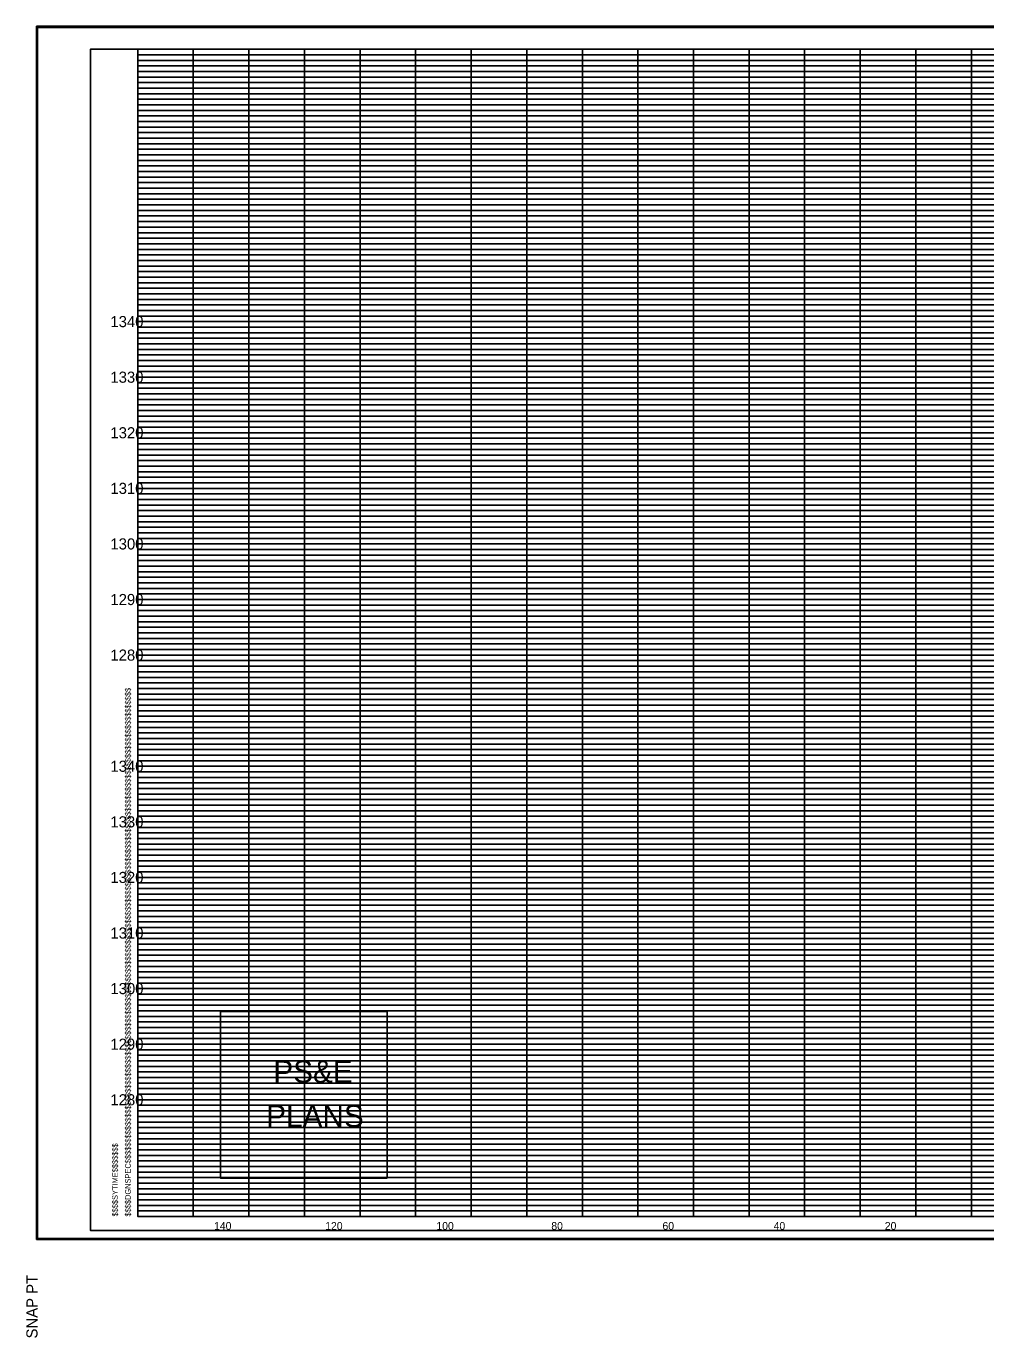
# Model space of a CAD drawing. Extents: x 980 to 1324, y 978 to 2847.
# Drawn here: x 979.9 to 1152.6, y 1248.2 to 1484.1 of the extents above; entities that cross this region are included whole.
import ezdxf

# ---------------------------------------------------------------- set-up
doc = ezdxf.new("R2010")
doc.units = 0
for name, color, linetype in [('DESIGN - SHEET - Corner Text', 7, 'Continuous'), ('DESIGN - SHEET - Light Grid', 7, 'Continuous'), ('DESIGN - SHEET - Linework', 7, 'Continuous'), ('DESIGN - SHEET - Plot Shape', 7, 'Continuous'), ('DESIGN - TYPICAL - Text', 7, 'Continuous')]:
    doc.layers.add(name, color=color, linetype=linetype)

# ---------------------------------------------------------------- blocks, each defined once
blk = doc.blocks.new('XSTSHT')
at = {"layer": 'DESIGN - SHEET - Light Grid'}
for p, q in [((0, 20.9), (8, 20.9)), ((0, 20.8), (8, 20.8)), ((8, 20.9), (16, 20.9)), ((8, 20.8), (16, 20.8)), ((0, 20.7), (8, 20.7)), ((0, 20.6), (8, 20.6)), ((8, 20.7), (16, 20.7)), ((8, 20.6), (16, 20.6)), ((0, 20.5), (8, 20.5)), ((0, 20.4), (8, 20.4)), ((0, 20.3), (8, 20.3)), ((8, 20.5), (16, 20.5)), ((8, 20.4), (16, 20.4)), ((8, 20.3), (16, 20.3)), ((0, 20.2), (8, 20.2)), ((0, 20.1), (8, 20.1)), ((8, 20.2), (16, 20.2)), ((8, 20.1), (16, 20.1)), ((0, 19.9), (8, 19.9)), ((8, 19.9), (16, 19.9)), ((0, 19.8), (8, 19.8)), ((0, 19.7), (8, 19.7)), ((0, 19.6), (8, 19.6)), ((8, 19.8), (16, 19.8)), ((8, 19.7), (16, 19.7)), ((8, 19.6), (16, 19.6)), ((0, 19.5), (8, 19.5)), ((0, 19.4), (8, 19.4)), ((8, 19.5), (16, 19.5)), ((8, 19.4), (16, 19.4)), ((0, 19.3), (8, 19.3)), ((0, 19.2), (8, 19.2)), ((8, 19.3), (16, 19.3)), ((8, 19.2), (16, 19.2)), ((0, 19.1), (8, 19.1)), ((0, 18.9), (8, 18.9)), ((8, 19.1), (16, 19.1)), ((8, 18.9), (16, 18.9)), ((0, 18.8), (8, 18.8)), ((0, 18.7), (8, 18.7)), ((8, 18.8), (16, 18.8)), ((8, 18.7), (16, 18.7)), ((0, 18.6), (8, 18.6)), ((0, 18.5), (8, 18.5)), ((8, 18.6), (16, 18.6)), ((8, 18.5), (16, 18.5)), ((0, 18.4), (8, 18.4)), ((0, 18.3), (8, 18.3)), ((0, 18.2), (8, 18.2)), ((8, 18.4), (16, 18.4)), ((8, 18.3), (16, 18.3)), ((8, 18.2), (16, 18.2)), ((0, 18.1), (8, 18.1)), ((8, 18.1), (16, 18.1)), ((0, 17.9), (8, 17.9)), ((0, 17.8), (8, 17.8)), ((0, 17.7), (8, 17.7)), ((8, 17.9), (16, 17.9)), ((8, 17.8), (16, 17.8)), ((8, 17.7), (16, 17.7)), ((0, 17.6), (8, 17.6)), ((0, 17.5), (8, 17.5)), ((8, 17.6), (16, 17.6)), ((8, 17.5), (16, 17.5)), ((0, 17.4), (8, 17.4)), ((0, 17.3), (8, 17.3)), ((8, 17.4), (16, 17.4)), ((8, 17.3), (16, 17.3)), ((0, 17.2), (8, 17.2)), ((0, 17.1), (8, 17.1)), ((8, 17.2), (16, 17.2)), ((8, 17.1), (16, 17.1)), ((0, 16.9), (8, 16.9)), ((0, 16.8), (8, 16.8)), ((8, 16.9), (16, 16.9)), ((8, 16.8), (16, 16.8)), ((0, 16.7), (8, 16.7)), ((0, 16.6), (8, 16.6)), ((8, 16.7), (16, 16.7)), ((8, 16.6), (16, 16.6)), ((0, 16.5), (8, 16.5)), ((0, 16.4), (8, 16.4)), ((0, 16.3), (8, 16.3)), ((8, 16.5), (16, 16.5)), ((8, 16.4), (16, 16.4)), ((8, 16.3), (16, 16.3)), ((0, 16.2), (8, 16.2)), ((0, 16.1), (8, 16.1)), ((8, 16.2), (16, 16.2)), ((8, 16.1), (16, 16.1)), ((0, 15.9), (8, 15.9)), ((8, 15.9), (16, 15.9)), ((0, 15.8), (8, 15.8)), ((0, 15.7), (8, 15.7)), ((0, 15.6), (8, 15.6)), ((8, 15.8), (16, 15.8)), ((8, 15.7), (16, 15.7)), ((8, 15.6), (16, 15.6)), ((0, 15.5), (8, 15.5)), ((0, 15.4), (8, 15.4)), ((8, 15.5), (16, 15.5)), ((8, 15.4), (16, 15.4)), ((0, 15.3), (8, 15.3)), ((0, 15.2), (8, 15.2)), ((8, 15.3), (16, 15.3)), ((8, 15.2), (16, 15.2)), ((0, 15.1), (8, 15.1)), ((0, 14.9), (8, 14.9)), ((8, 15.1), (16, 15.1)), ((8, 14.9), (16, 14.9)), ((0, 14.8), (8, 14.8)), ((0, 14.7), (8, 14.7)), ((8, 14.8), (16, 14.8)), ((8, 14.7), (16, 14.7)), ((0, 14.6), (8, 14.6)), ((0, 14.5), (8, 14.5)), ((0, 14.4), (8, 14.4)), ((8, 14.6), (16, 14.6)), ((8, 14.5), (16, 14.5)), ((8, 14.4), (16, 14.4)), ((0, 14.3), (8, 14.3)), ((0, 14.2), (8, 14.2)), ((8, 14.3), (16, 14.3)), ((8, 14.2), (16, 14.2)), ((0, 14.1), (8, 14.1)), ((8, 14.1), (16, 14.1)), ((0, 13.9), (8, 13.9)), ((0, 13.8), (8, 13.8)), ((0, 13.7), (8, 13.7)), ((8, 13.9), (16, 13.9)), ((8, 13.8), (16, 13.8)), ((8, 13.7), (16, 13.7)), ((0, 13.6), (8, 13.6)), ((0, 13.5), (8, 13.5)), ((8, 13.6), (16, 13.6)), ((8, 13.5), (16, 13.5)), ((0, 13.4), (8, 13.4)), ((0, 13.3), (8, 13.3)), ((8, 13.4), (16, 13.4)), ((8, 13.3), (16, 13.3)), ((0, 13.2), (8, 13.2)), ((0, 13.1), (8, 13.1)), ((8, 13.2), (16, 13.2)), ((8, 13.1), (16, 13.1)), ((0, 12.9), (8, 12.9)), ((0, 12.8), (8, 12.8)), ((8, 12.9), (16, 12.9)), ((8, 12.8), (16, 12.8)), ((0, 12.7), (8, 12.7)), ((0, 12.6), (8, 12.6)), ((8, 12.7), (16, 12.7)), ((8, 12.6), (16, 12.6)), ((0, 12.5), (8, 12.5)), ((0, 12.4), (8, 12.4)), ((0, 12.3), (8, 12.3)), ((8, 12.5), (16, 12.5)), ((8, 12.4), (16, 12.4)), ((8, 12.3), (16, 12.3)), ((0, 12.2), (8, 12.2)), ((0, 12.1), (8, 12.1)), ((8, 12.2), (16, 12.2)), ((8, 12.1), (16, 12.1)), ((0, 11.9), (8, 11.9)), ((0, 11.8), (8, 11.8)), ((8, 11.9), (16, 11.9)), ((8, 11.8), (16, 11.8)), ((0, 11.7), (8, 11.7)), ((0, 11.6), (8, 11.6)), ((8, 11.7), (16, 11.7)), ((8, 11.6), (16, 11.6)), ((0, 11.5), (8, 11.5)), ((0, 11.4), (8, 11.4)), ((8, 11.5), (16, 11.5)), ((8, 11.4), (16, 11.4)), ((0, 11.3), (8, 11.3)), ((0, 11.2), (8, 11.2)), ((0, 11.1), (8, 11.1)), ((8, 11.3), (16, 11.3)), ((8, 11.2), (16, 11.2)), ((8, 11.1), (16, 11.1)), ((0, 10.9), (8, 10.9)), ((8, 10.9), (16, 10.9)), ((0, 10.8), (8, 10.8)), ((0, 10.7), (8, 10.7)), ((8, 10.8), (16, 10.8)), ((8, 10.7), (16, 10.7)), ((0, 10.6), (8, 10.6)), ((0, 10.5), (8, 10.5)), ((0, 10.4), (8, 10.4)), ((8, 10.6), (16, 10.6)), ((8, 10.5), (16, 10.5)), ((8, 10.4), (16, 10.4)), ((0, 10.3), (8, 10.3)), ((0, 10.2), (8, 10.2)), ((8, 10.3), (16, 10.3)), ((8, 10.2), (16, 10.2)), ((0, 10.1), (8, 10.1)), ((8, 10.1), (16, 10.1)), ((0, 9.9), (8, 9.9)), ((0, 9.8), (8, 9.8)), ((0, 9.7), (8, 9.7)), ((8, 9.9), (16, 9.9)), ((8, 9.8), (16, 9.8)), ((8, 9.7), (16, 9.7)), ((0, 9.6), (8, 9.6)), ((0, 9.5), (8, 9.5)), ((8, 9.6), (16, 9.6)), ((8, 9.5), (16, 9.5)), ((0, 9.4), (8, 9.4)), ((0, 9.3), (8, 9.3)), ((8, 9.4), (16, 9.4)), ((8, 9.3), (16, 9.3)), ((0, 9.2), (8, 9.2)), ((0, 9.1), (8, 9.1)), ((8, 9.2), (16, 9.2)), ((8, 9.1), (16, 9.1)), ((0, 8.9), (8, 8.9)), ((0, 8.8), (8, 8.8)), ((8, 8.9), (16, 8.9)), ((8, 8.8), (16, 8.8)), ((0, 8.7), (8, 8.7)), ((0, 8.6), (8, 8.6)), ((0, 8.5), (8, 8.5)), ((8, 8.7), (16, 8.7)), ((8, 8.6), (16, 8.6)), ((8, 8.5), (16, 8.5)), ((0, 8.4), (8, 8.4)), ((0, 8.3), (8, 8.3)), ((8, 8.4), (16, 8.4)), ((8, 8.3), (16, 8.3)), ((0, 8.2), (8, 8.2)), ((0, 8.1), (8, 8.1)), ((8, 8.2), (16, 8.2)), ((8, 8.1), (16, 8.1)), ((0, 7.9), (8, 7.9)), ((0, 7.8), (8, 7.8)), ((8, 7.9), (16, 7.9)), ((8, 7.8), (16, 7.8)), ((0, 7.7), (8, 7.7)), ((0, 7.6), (8, 7.6)), ((8, 7.7), (16, 7.7)), ((8, 7.6), (16, 7.6)), ((0, 7.5), (8, 7.5)), ((0, 7.4), (8, 7.4)), ((8, 7.5), (16, 7.5)), ((8, 7.4), (16, 7.4)), ((0, 7.3), (8, 7.3)), ((0, 7.2), (8, 7.2)), ((0, 7.1), (8, 7.1)), ((8, 7.3), (16, 7.3)), ((8, 7.2), (16, 7.2)), ((8, 7.1), (16, 7.1)), ((0, 6.9), (8, 6.9)), ((8, 6.9), (16, 6.9)), ((0, 6.8), (8, 6.8)), ((0, 6.7), (8, 6.7)), ((8, 6.8), (16, 6.8)), ((8, 6.7), (16, 6.7)), ((0, 6.6), (8, 6.6)), ((0, 6.5), (8, 6.5)), ((0, 6.4), (8, 6.4)), ((8, 6.6), (16, 6.6)), ((8, 6.5), (16, 6.5)), ((8, 6.4), (16, 6.4)), ((0, 6.3), (8, 6.3)), ((0, 6.2), (8, 6.2)), ((8, 6.3), (16, 6.3)), ((8, 6.2), (16, 6.2)), ((0, 6.1), (8, 6.1)), ((0, 5.9), (8, 5.9)), ((8, 6.1), (16, 6.1)), ((8, 5.9), (16, 5.9)), ((0, 5.8), (8, 5.8)), ((0, 5.7), (8, 5.7)), ((8, 5.8), (16, 5.8)), ((8, 5.7), (16, 5.7)), ((0, 5.6), (8, 5.6)), ((0, 5.5), (8, 5.5)), ((8, 5.6), (16, 5.6)), ((8, 5.5), (16, 5.5)), ((0, 5.4), (8, 5.4)), ((0, 5.3), (8, 5.3)), ((0, 5.2), (8, 5.2)), ((8, 5.4), (16, 5.4)), ((8, 5.3), (16, 5.3)), ((8, 5.2), (16, 5.2)), ((0, 5.1), (8, 5.1)), ((8, 5.1), (16, 5.1)), ((0, 4.9), (8, 4.9)), ((0, 4.8), (8, 4.8)), ((8, 4.9), (16, 4.9)), ((8, 4.8), (16, 4.8)), ((0, 4.7), (8, 4.7)), ((0, 4.6), (8, 4.6)), ((0, 4.5), (8, 4.5)), ((8, 4.7), (16, 4.7)), ((8, 4.6), (16, 4.6)), ((8, 4.5), (16, 4.5)), ((0, 4.4), (8, 4.4)), ((0, 4.3), (8, 4.3)), ((8, 4.4), (16, 4.4)), ((8, 4.3), (16, 4.3)), ((0, 4.2), (8, 4.2)), ((0, 4.1), (8, 4.1)), ((8, 4.2), (16, 4.2)), ((8, 4.1), (16, 4.1)), ((0, 3.9), (8, 3.9)), ((0, 3.8), (8, 3.8)), ((8, 3.9), (16, 3.9)), ((8, 3.8), (16, 3.8)), ((0, 3.7), (8, 3.7)), ((0, 3.6), (8, 3.6)), ((8, 3.7), (16, 3.7)), ((8, 3.6), (16, 3.6)), ((0, 3.5), (8, 3.5)), ((0, 3.4), (8, 3.4)), ((8, 3.5), (16, 3.5)), ((8, 3.4), (16, 3.4)), ((0, 3.3), (8, 3.3)), ((0, 3.2), (8, 3.2)), ((0, 3.1), (8, 3.1)), ((8, 3.3), (16, 3.3)), ((8, 3.2), (16, 3.2)), ((8, 3.1), (16, 3.1)), ((0, 2.9), (8, 2.9)), ((8, 2.9), (16, 2.9)), ((0, 2.8), (8, 2.8)), ((0, 2.7), (8, 2.7)), ((0, 2.6), (8, 2.6)), ((8, 2.8), (16, 2.8)), ((8, 2.7), (16, 2.7)), ((8, 2.6), (16, 2.6)), ((0, 2.5), (8, 2.5)), ((0, 2.4), (8, 2.4)), ((8, 2.5), (16, 2.5)), ((8, 2.4), (16, 2.4)), ((0, 2.3), (8, 2.3)), ((0, 2.2), (8, 2.2)), ((8, 2.3), (16, 2.3)), ((8, 2.2), (16, 2.2)), ((0, 2.1), (8, 2.1)), ((0, 1.9), (8, 1.9)), ((8, 2.1), (16, 2.1)), ((8, 1.9), (16, 1.9)), ((0, 1.8), (8, 1.8)), ((0, 1.7), (8, 1.7)), ((8, 1.8), (16, 1.8)), ((8, 1.7), (16, 1.7)), ((0, 1.6), (8, 1.6)), ((0, 1.5), (8, 1.5)), ((8, 1.6), (16, 1.6)), ((8, 1.5), (16, 1.5)), ((0, 1.4), (8, 1.4)), ((0, 1.3), (8, 1.3)), ((0, 1.2), (8, 1.2)), ((8, 1.4), (16, 1.4)), ((8, 1.3), (16, 1.3)), ((8, 1.2), (16, 1.2)), ((0, 1.1), (8, 1.1)), ((8, 1.1), (16, 1.1)), ((0, 0.9), (8, 0.9)), ((0, 0.8), (8, 0.8)), ((8, 0.9), (16, 0.9)), ((8, 0.8), (16, 0.8)), ((0, 0.7), (8, 0.7)), ((0, 0.6), (8, 0.6)), ((0, 0.5), (8, 0.5)), ((8, 0.7), (16, 0.7)), ((8, 0.6), (16, 0.6)), ((8, 0.5), (16, 0.5)), ((0, 0.4), (8, 0.4)), ((0, 0.3), (8, 0.3)), ((8, 0.4), (16, 0.4)), ((8, 0.3), (16, 0.3)), ((0, 0.2), (8, 0.2)), ((0, 0.1), (8, 0.1)), ((8, 0.2), (16, 0.2)), ((8, 0.1), (16, 0.1))]:
    blk.add_line(p, q, dxfattribs=at)
at = {"layer": 'DESIGN - SHEET - Linework'}
for p, q in [((-1.823, -0.414), (-1.823, 21.414)), ((-1.823, 21.414), (32.217, 21.414)), ((1, 0), (1, 21)), ((2, 0), (2, 21)), ((3, 0), (3, 21)), ((4, 0), (4, 21)), ((5, 0), (5, 21)), ((6, 0), (6, 21)), ((7, 0), (7, 21)), ((8, 0), (8, 21)), ((9, 0), (9, 21)), ((10, 0), (10, 21)), ((11, 0), (11, 21)), ((12, 0), (12, 21)), ((13, 0), (13, 21)), ((14, 0), (14, 21)), ((15, 0), (15, 21)), ((0, 20), (28, 20)), ((0, 19), (32, 19)), ((0, 18), (32, 18)), ((0, 17), (32, 17)), ((0, 16), (32, 16)), ((0, 15), (32, 15)), ((0, 14), (32, 14)), ((0, 13), (32, 13)), ((0, 12), (32, 12)), ((0, 11), (32, 11)), ((0, 10), (32, 10)), ((0, 9), (32, 9)), ((0, 8), (32, 8)), ((0, 7), (32, 7)), ((0, 6), (32, 6)), ((0, 5), (32, 5)), ((0, 4), (32, 4)), ((0, 3), (32, 3)), ((0, 2), (32, 2)), ((0, 1), (32, 1)), ((-1.823, -0.414), (32.217, -0.414))]:
    blk.add_line(p, q, dxfattribs=at)
blk.add_lwpolyline([(0, 21), (0, 0), (32, 0), (32, 21), (0, 21)], dxfattribs=at)
at = {"layer": 'DESIGN - SHEET - Plot Shape'}
for points in [[(-1.803, 21.394), (32.197, 21.394), (32.197, -0.394), (-1.803, -0.394)], [(-0.85, 21), (32, 21), (32, -0.25), (-0.85, -0.25)]]:
    blk.add_lwpolyline(points, close=True, dxfattribs=at)
at = {"layer": 'DESIGN - SHEET - Corner Text'}
for s, height, p in [('$$$$DGNSPEC$$$$$$$$$$$$$$$$$$$$$$$$$$$$$$$$$$$$$$$$$$$$$$$$$$$$$$$$$$$$$$$$$$$$$$$$$$$$$$$$$$$$$$$$$$$$$$$$$$$$$$$$$$$$$$$$$$$', 0.100002, (-0.126, 0)), ('$$$$SYTIME$$$$$$$', 0.1, (-0.358, 0)), ('SNAP PT  ', 0.2, (-1.803, -2.194))]:
    blk.add_text(s, height=height, rotation=90, dxfattribs=at).set_placement(p)

msp = doc.modelspace()

# ---------------------------------------------------------------- linework, layer by layer
at = {"layer": 'DESIGN - SHEET - Corner Text'}
msp.add_lwpolyline([(1014.88, 1306.91), (1014.88, 1276.91), (1044.88, 1276.91), (1044.88, 1306.91)], close=True, dxfattribs=at)
at = {"layer": 'DESIGN - SHEET - Plot Shape'}
msp.add_lwpolyline([(991.5, 1267.5), (1320, 1267.5), (1320, 1480), (991.5, 1480)], close=True, dxfattribs=at)

# ---------------------------------------------------------------- block references
at = {"layer": 'DESIGN - SHEET - Plot Shape', "xscale": 10, "yscale": 10}
msp.add_blockref('XSTSHT', (1000, 1270), dxfattribs=at)

# ---------------------------------------------------------------- texts
at = {"layer": 'DESIGN - SHEET - Corner Text'}
for s, p in [('PS&E', (1024.4, 1294.08)), ('PLANS', (1023.12, 1286.08))]:
    msp.add_text(s, height=4, dxfattribs=at).set_placement(p)
at = {"layer": 'DESIGN - TYPICAL - Text'}
for s, height, p in [('     1340     ', 2, (991.37, 1430)), ('     1330     ', 2, (991.37, 1420)), ('     1320     ', 2, (991.37, 1410)), ('     1310     ', 2, (991.37, 1400)), ('     1300     ', 2, (991.37, 1390)), ('     1290     ', 2, (991.37, 1380)), ('     1280     ', 2, (991.37, 1370)), ('     1340     ', 2, (991.37, 1350)), ('     1330     ', 2, (991.37, 1340)), ('     1320     ', 2, (991.37, 1330)), ('     1310     ', 2, (991.37, 1320)), ('     1300     ', 2, (991.37, 1310)), ('     1290     ', 2, (991.37, 1300)), ('     1280     ', 2, (991.37, 1290)), ('     140     ', 1.4, (1011.14, 1267.6)), ('     120     ', 1.4, (1031.14, 1267.6)), ('     100     ', 1.4, (1051.14, 1267.6)), ('     80     ', 1.4, (1071.82, 1267.6)), ('     60     ', 1.4, (1091.82, 1267.6)), ('     40     ', 1.4, (1111.82, 1267.6)), ('     20     ', 1.4, (1131.82, 1267.6))]:
    msp.add_text(s, height=height, dxfattribs=at).set_placement(p)

doc.saveas('drawing.dxf')
